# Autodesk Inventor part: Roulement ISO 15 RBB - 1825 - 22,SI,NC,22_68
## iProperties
Created: 2011-01
Part Number: Roulement ISO 15 RBB - 1825 - 22,SI,NC,22_68
Document SubType Name: Modeling
Designer: eric
Density: 1 g/cm^3
Mass: 3.22079 g
Surface Area: 33.6699 cm^2
Volume: 3.22079 cm^3
Author: eric
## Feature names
1. Base1
